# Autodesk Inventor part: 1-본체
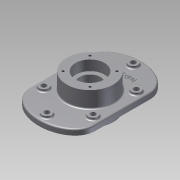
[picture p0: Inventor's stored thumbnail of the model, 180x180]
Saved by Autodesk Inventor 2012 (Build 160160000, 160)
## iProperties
Created: 2015-02
Part Number: 1-본체
Material: Default
Document SubType Name: Modeling
Designer: Administrator
Density: 1 g/cm^3
Author: Administrator
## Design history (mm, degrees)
sketch "스케치1"
  geometry: L1 (-70, -60)-(-70, 0); L2 (70, -60)-(70, 0); L3 (-70, 60)-(-70, 0); L4 (70, 60)-(70, 0); 3 further points; 2 other entities
  constraints: 8 end point, 3 vertical, 1 parallel, 8 other
extrude "돌출1" new body sketch "스케치1" distance "d4" = 12; taper "d5" = 0 deg
node "작업 평면1"
sketch "스케치11"
  geometry: L1 (-70, -60)-(-70, 60) reference; L2 (-70, 60)-(-70, 46.5); L3 (-70, 46.5)-(-53, 46.5); L4 (-70, -60)-(-70, -46.5); C1 r 10 at (-53, 46.5); C2 r 10 at (-53, -46.5); C3 r 10 at (0, 93); C4 r 10 at (53, 46.5); C5 r 10 at (53, -46.5); C6 r 10 at (0, -93); 1 further point
  constraints: 6 centre point, 6 end point, 2 point on line, 1 coincident
  dimensions: "d49" = 20 diameter of C1; "d51" = 20 diameter of C3; "d52" = 20 diameter of C4; "d54" = 20 diameter of C6
extrude "돌출8" join sketch "스케치11" distance "d55" = 5; taper "d56" = 0 deg
node "작업 평면2"
sketch "스케치12"
  geometry: C1 r 50 at (0, 0); 1 further point
  constraints: 1 centre point, 1 coincident
  dimensions: "d58" = 100 diameter of C1
extrude "돌출9" join sketch "스케치12" distance "d59" = 70; taper "d60" = 0 deg
sketch "스케치13"
  geometry: C1 r 50 at (0, 0) reference; C2 r 31 at (0, 0)
  constraints: 1 centre point, 1 coincident
  dimensions: "d61" = 62 diameter of C2
extrude "돌출10" cut sketch "스케치13" distance "d62" = 22; taper "d63" = 0 deg
sketch "스케치14"
  geometry: C1 r 50 at (0, 0) reference; C2 r 31 at (0, 0)
  constraints: 1 centre point, 1 coincident
  dimensions: "d64" = 62 diameter of C2
extrude "돌출11" cut sketch "스케치14" distance "d65" = 22; taper "d66" = 0 deg
sketch "스케치15"
  geometry: C1 r 31 at (0, 0) reference; C2 r 22.5 at (0, 0)
  constraints: 1 centre point, 1 coincident
  dimensions: "d67" = 45 diameter of C2
extrude "돌출12" cut sketch "스케치15" stored distance "d68" = 22; taper "d69" = 0 deg
sketch "스케치16"
  geometry: C1 r 10 at (0, 0) reference; C2 r 10 at (-53, -46.5) reference; C3 r 10 at (53, -46.5) reference; C4 r 10 at (53, -139.5) reference; C5 r 10 at (0, -186) reference; C6 r 10 at (-53, -139.5) reference; C7 r 5.5 at (0, 0); C8 r 5.5 at (53, -46.5); C9 r 5.5 at (-53, -46.5); C10 r 5.5 at (-53, -139.5); C11 r 5.5 at (53, -139.5); C12 r 5.5 at (0, -186); 1 further point
  constraints: 6 centre point, 1 coincident
extrude "돌출13" cut sketch "스케치16" stored distance "d71" = 22; taper "d72" = 0 deg
sketch "스케치17"
  geometry: L1 (0, 0)-(-58.647, 0); C1 r 50 at (0, 0) reference; 1 further point
  constraints: 2 end point, 1 horizontal
hole "구멍1" sketch "스케치17" at (-28.991, 28.991) diameter "d75" = 4.917; stored, may be unused: countersink angle "d79" = 90 deg, drill point angle "d81" = 118 deg; dims "d76" = 10, "d77" = 4, "d78" = 2, "d80" = 13
sketch "스케치18"
  geometry: 1 further point
hole "구멍2" sketch "스케치18" at (-28.991, 28.991) diameter "d87" = 4.917; stored, may be unused: countersink angle "d91" = 90 deg, drill point angle "d93" = 118 deg; dims "d88" = 10, "d89" = 4, "d90" = 2, "d92" = 13
fillet "모깎기1" dims "d97" = 3, "d98" = 0.3
sketch "스케치19"
  geometry: 1 further point
  constraints: 1 other
feature "엠보싱1" sketch "스케치19" dims "d100" = 1, "d101" = 0
node "솔리드1"
pattern_circular "원형 패턴1" dims angle "d83" = 360 deg
pattern_circular "원형 패턴2" dims angle "d95" = 360 deg
node "투영된 루프6"
node "투영된 루프7"
node "투영된 루프8"
node "투영된 루프9"
node "투영된 루프10"
other parameters: "d6" = -23, "d57" = -23
